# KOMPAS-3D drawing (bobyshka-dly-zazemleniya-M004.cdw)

Referenced files: Бобышка для слива.cdw
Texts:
  Бобышка для слива
  Луконнен Н.Д.
  ООО "ХСМ"
  Ra 12,5
  Бобышка
  для слива
Dimensions and other numbers on the sheet: 12; 40; 26; 32; 20; 1,5; 1:1; 1; 0,14; 0; 2; 3; 4; 5; 6; 7; 8; 9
